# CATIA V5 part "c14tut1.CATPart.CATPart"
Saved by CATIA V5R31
Part number: Part1
Bounding box of the stored display mesh (mm): x 0 to 46, y -104 to 104, z 0 to 68
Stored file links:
  D:\PROJECTS\Project 2021\US EDITION\CATIA V5 6R 2021\Resources\Tutorial Files\c14_catia_v5_6r2021_tut\c14tut1\c14tut1.CATPart.CATPart
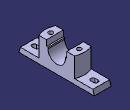
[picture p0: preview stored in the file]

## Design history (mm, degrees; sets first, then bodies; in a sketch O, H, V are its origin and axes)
Body1 (main body)
  Sketch1 on yz-plane, origin (0, 0, 0), H (0, 1, 0), V (0, 0, 1)
    axis line L1 (0, -39.4814) -> (0, 63.0107)
    point P1 (0, -39.4814)
    line L2 (0, 0) -> (104, 0)
    point P3 (104, 0)
    line L3 (104, 0) -> (100, 14)
    point P4 (100, 14)
    line L4 (100, 14) -> (54, 14)
    point P5 (54, 14)
    line L5 (54, 14) -> (54, 68)
    point P6 (54, 68)
    line L6 (54, 68) -> (28, 68)
    point P7 (28, 68)
    line L7 (28, 68) -> (28, 52)
    point P8 (28, 52)
    line L8 (28, 52) -> (24, 52)
    point P9 (24, 52)
    point P10 (0, 24)
    point P11 (-104, 0)
    point P12 (0, 0)
    line L9 (0, 0) -> (-104, 0)
    point P13 (0, 24)
    point P14 (-24, 52)
    point P15 (6.1714, 48)
    point P16 (-54, 68)
    point P17 (-28, 68)
    point P18 (-28, 52)
    line L10 (-54, 68) -> (-28, 68)
    line L11 (-28, 68) -> (-28, 52)
    line L12 (-28, 52) -> (-24, 52)
    point P19 (-54, 14)
    line L13 (-54, 14) -> (-54, 68)
    point P20 (-100, 14)
    line L14 (-100, 14) -> (-54, 14)
    line L15 (-104, 0) -> (-100, 14)
    line L16 (-24, 52) -> (-24, 48)
    line L17 (24, 52) -> (24, 48)
    arc A1 centre (0, 48) radius 24 from (-24, 48) to (24, 48) ccw
    point P23 (0, 48)
    point P24 (0, 24)
    distance P3 P11 = 208
    length L3 V = 14
    distance P17 P7 = 56
    distance P18 P17 = 16
    length L15 H = 4
    distance L6 L2 = 68
    distance L12 P23 = 4
    radius A1 = 24
    distance L13 L5 = 108
    coincidence: P1 V, L1 P10, O P12, P10 P13, A1 P24, P24 L1
    vertical: L1 V, L5 V, L7 V, L16 V, L17 V
    horizontal: L2 H, L4 H, L6 H, L8 H
    symmetry: P3 P11 L1, O P12 L1, L2 L9 L1, P10 P13 L1, P9 P14 L1, P6 P16 L1, P7 P17 L1, P8 P18 L1, L6 L10 L1, L7 L11 L1, L8 L12 L1, P5 P19 L1, L5 L13 L1, P4 P20 L1, L4 L14 L1, L3 L15 L1
    tangency: A1 L17, L16 A1
  Pad1: profile Sketch1, direction (1, 0, 0), length 46
  Sketch2 on face of Pad1, origin (0, 0, 14), H (1, 0, 0), V (0, 1, 0)
    circle A1 centre (23, 0) radius 54
    point P1 (23, 0)
    reference projected line E1 (46, 100) -> (46, 54) from edge [face of Pad1 from Sketch1.L4 | end face of Pad1]
    radius A1 = 54
    distance P1 E1 = 23
    coincidence: P1 H
  Pocket1: profile Sketch2, direction (0, 0, 1), through (limit type 3), outer side
  Sketch3 on face of Pad1 from Sketch1.L9, origin (0, 0, 0), H (1, 0, 0), V (0, -1, 0)
    point P1 (23, 39)
    line L1 (36, 52) -> (36, 26)
    line L2 (36, 26) -> (10, 26)
    line L3 (10, 26) -> (10, 52)
    line L4 (10, 52) -> (36, 52)
    reference intersected line E1 (0, 104) -> (46, 104) from face of Pad1
    reference projected line E2 (0, 104) -> (0, 0) from edge [start face of Pad1 | face of Pad1 from Sketch1.L9]
    length L3 = 26
    length L4 = 26
    distance L2 E1 = 78
    distance L3 E2 = 10
    vertical: L1 V, L3 V
    horizontal: L2 H, L4 H
    equidistance: L1 L3 P1, L2 L4 P1
  Pocket2: profile Sketch3, direction (0, 0, 1), length 10
  Sketch4 on face of Pad1, origin (24.629, 46.0353, 68), H (1, 0, 0), V (0, 1, 0)
    point P1 (-1.629, -85.0353)
    axis line L1 (11.371, -98.0353) -> (-14.629, -72.0353)
    point P2 (11.371, -98.0353)
    point P3 (-14.629, -72.0353)
    reference projected point E1 (11.371, -98.0353) from vertex [face of Pocket2 | face of Pocket2 | face of Pocket2]
    reference projected point E2 (-14.629, -72.0353) from vertex [face of Pocket2 | face of Pocket2 | face of Pocket2]
    coincidence: P2 E1, P3 E2
    midpoint: P1 L1
  Hole1: placed by Sketch4, at (23, -39, 68) direction (0, 0, -1), diameter 12, depth 100, V-bottom angle 120
  Sketch5 on face of Pad1, origin (0, 0, 14), H (1, 0, 0), V (0, 1, 0)
    construction line L1 (23, -77) -> (23, -85)
    point P2 (23, -85)
    line L2 (29, -77) -> (29, -85)
    line L3 (17, -85) -> (17, -77)
    arc A1 centre (23, -85) radius 6 from (29, -85) to (17, -85) cw
    arc A2 centre (23, -77) radius 6 from (17, -77) to (29, -77) cw
    reference projected line E1 (46, -54) -> (46, -100) from edge of Pad1
    reference projected line E2 (0, -104) -> (46, -104) from edge [face of Pad1 | face of Pad1]
    distance L1 E1 = 23
    distance P2 E2 = 19
    radius A1 = 6
    length L1 = 8
    vertical: L1 V
    tangency: A1 L2, A2 L2, A1 L3, A2 L3
    parallelism: L1 L2
  Pocket3: profile Sketch5, direction (0, 0, -1), through (limit type 3)
  Mirror1: of Pocket2, Hole1, Pocket3, about zx-plane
